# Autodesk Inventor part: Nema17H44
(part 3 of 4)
sketch "Эскиз112" dims "d52" = 8, "d53" = 4, "d55" = 5, "d56" = 11, "d57" = 12.2, "d58" = 6.1, "d60" = 36, "d61" = 45, "d62" = 50 (= 0.5 x h1), "d63" = 8.1, "d64" = 5, "d65" = 3, "d66" = 5.7
  geometry: L1 (-16.714, 19.577)-(-16.716, 18.63) reference; L2 (-16.08, 18.353)-(-16.08, 17.853) reference; L3 (-16.718, 17.574)-(-16.72, 16.633) reference; L4 (-16.08, 16.353)-(-16.08, 15.853) reference; L5 (-16.723, 15.571)-(-16.725, 14.636) reference; L6 (-16.08, 14.353)-(-16.08, 13.853) reference; L7 (-16.727, 13.569)-(-16.729, 12.639) reference; L8 (-16.08, 12.353)-(-16.08, 11.853) reference; L9 (-16.732, 11.566)-(-16.734, 10.642) reference; L10 (-16.08, 10.353)-(-16.08, 9.853) reference; L11 (-16.736, 9.563)-(-16.738, 8.645) reference; L12 (-16.08, 8.353)-(-16.08, 7.853) reference; L13 (-16.741, 7.56)-(-16.743, 6.648) reference; L14 (-16.08, 6.353)-(-16.08, 5.853) reference; L15 (-16.745, 5.556)-(-16.747, 4.651) reference; L16 (-16.08, 4.353)-(-16.08, 3.853) reference; L17 (-16.749, 3.553)-(-16.751, 2.654) reference; L18 (-16.08, 2.353)-(-16.08, 1.853) reference; L19 (-16.754, 1.55)-(-16.756, 0.657) reference; L20 (-16.08, 0.353)-(-16.08, -0.147) reference; L21 (-16.758, -0.453)-(-16.76, -1.339) reference; L22 (-16.08, -1.647)-(-16.08, -2.147) reference; L23 (-16.763, -2.457)-(-17, -108.975) reference; L24 (-29, -108.975)-(-29.55, 138.024) reference; L25 (-16.45, 138.024)-(-16.703, 24.622) reference; L26 (-16.08, 24.353)-(-16.08, 23.853) reference; L27 (-16.705, 23.582)-(-16.707, 22.625) reference; L28 (-16.08, 22.353)-(-16.08, 21.853) reference; L29 (-16.709, 21.58)-(-16.711, 20.628) reference; L30 (-16.08, 20.353)-(-16.08, 19.853) reference; L31 (-15.6, -108.962)-(-15.6, 138.038) reference; L32 (-30.4, 138.038)-(-30.4, -108.962) reference; L33 (-16.18, 1.853)-(-16.18, 2.353); L34 (-16.852, 2.606)-(-16.849, 3.602); L35 (-16.18, 3.853)-(-16.18, 4.353); L36 (-16.847, 4.602)-(-16.845, 5.606); L37 (-16.18, 5.853)-(-16.18, 6.353); L38 (-16.843, 6.598)-(-16.84, 7.609); L39 (-16.18, 7.853)-(-16.18, 8.353); L40 (-16.838, 8.595)-(-16.836, 9.613); L41 (-16.18, 9.853)-(-16.18, 10.353); L42 (-16.834, 10.591)-(-16.831, 11.617); L43 (-16.18, 11.853)-(-16.18, 12.353); L44 (-16.829, 12.588)-(-16.827, 13.62); L45 (-16.18, 13.853)-(-16.18, 14.353); L46 (-16.825, 14.584)-(-16.823, 15.624); L47 (-16.18, 15.853)-(-16.18, 16.353); L48 (-16.82, 16.581)-(-16.818, 17.627); L49 (-16.18, 17.853)-(-16.18, 18.353); L50 (-16.816, 18.577)-(-16.814, 19.63); L51 (-16.18, 19.853)-(-16.18, 20.353); L52 (-16.812, 20.574)-(-16.809, 21.633); L53 (-16.18, 21.853)-(-16.18, 22.353); L54 (-16.807, 22.571)-(-16.805, 23.637); L55 (-16.18, 23.853)-(-16.18, 24.353); L56 (-16.803, 24.568)-(-16.55, 138.024); L57 (-29.45, 138.024)-(-28.9, -108.975); L58 (-17.1, -108.975)-(-16.863, -2.41); L59 (-16.18, -2.147)-(-16.18, -1.647); L60 (-16.86, -1.386)-(-16.858, -0.406); L61 (-16.18, -0.147)-(-16.18, 0.353); L62 (-16.856, 0.61)-(-16.854, 1.598); L63 (-17, 22.5)-(0, 22.5) reference; L64 (-15.5, 22.5)-(-15.5, -0.147)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; C1 r 1 at (-14.5, 15.25) reference; C2 r 1 at (-14.5, 7.25) reference; A1 r 0.555 centre (-16.425, 19.103) between (-16.668, 19.602) and (-16.714, 19.577) reference; A2 r 0.555 centre (-16.425, 19.103) between (-16.716, 18.63) and (-16.668, 18.604) reference; A3 r 1 centre (-16.23, 19.503) between (-16.668, 18.604) and (-16.23, 18.503) reference; A4 r 0.15 centre (-16.23, 18.353) between (-16.08, 18.353) and (-16.23, 18.503) reference; A5 r 0.15 centre (-16.23, 17.853) between (-16.23, 17.703) and (-16.08, 17.853) reference; A6 r 1 centre (-16.23, 16.703) between (-16.23, 17.703) and (-16.668, 17.602) reference; A7 r 0.555 centre (-16.425, 17.103) between (-16.668, 17.602) and (-16.718, 17.574) reference; A8 r 0.555 centre (-16.425, 17.103) between (-16.72, 16.633) and (-16.668, 16.604) reference; A9 r 1 centre (-16.23, 17.503) between (-16.668, 16.604) and (-16.23, 16.503) reference; A10 r 0.15 centre (-16.23, 16.353) between (-16.08, 16.353) and (-16.23, 16.503) reference; A11 r 0.15 centre (-16.23, 15.853) between (-16.23, 15.703) and (-16.08, 15.853) reference; A12 r 1 centre (-16.23, 14.703) between (-16.23, 15.703) and (-16.668, 15.602) reference; A13 r 0.555 centre (-16.425, 15.103) between (-16.668, 15.602) and (-16.723, 15.571) reference; A14 r 0.555 centre (-16.425, 15.103) between (-16.725, 14.636) and (-16.668, 14.604) reference; A15 r 1 centre (-16.23, 15.503) between (-16.668, 14.604) and (-16.23, 14.503) reference; A16 r 0.15 centre (-16.23, 14.353) between (-16.08, 14.353) and (-16.23, 14.503) reference; A17 r 0.15 centre (-16.23, 13.853) between (-16.23, 13.703) and (-16.08, 13.853) reference; A18 r 1 centre (-16.23, 12.703) between (-16.23, 13.703) and (-16.668, 13.602) reference; A19 r 0.555 centre (-16.425, 13.103) between (-16.668, 13.602) and (-16.727, 13.569) reference; A20 r 0.555 centre (-16.425, 13.103) between (-16.729, 12.639) and (-16.668, 12.604) reference; A21 r 1 centre (-16.23, 13.503) between (-16.668, 12.604) and (-16.23, 12.503) reference; A22 r 0.15 centre (-16.23, 12.353) between (-16.08, 12.353) and (-16.23, 12.503) reference; A23 r 0.15 centre (-16.23, 11.853) between (-16.23, 11.703) and (-16.08, 11.853) reference; A24 r 1 centre (-16.23, 10.703) between (-16.23, 11.703) and (-16.668, 11.602) reference; A25 r 0.555 centre (-16.425, 11.103) between (-16.668, 11.602) and (-16.732, 11.566) reference; A26 r 0.555 centre (-16.425, 11.103) between (-16.734, 10.642) and (-16.668, 10.604) reference; A27 r 1 centre (-16.23, 11.503) between (-16.668, 10.604) and (-16.23, 10.503) reference; A28 r 0.15 centre (-16.23, 10.353) between (-16.08, 10.353) and (-16.23, 10.503) reference; A29 r 0.15 centre (-16.23, 9.853) between (-16.23, 9.703) and (-16.08, 9.853) reference; A30 r 1 centre (-16.23, 8.703) between (-16.23, 9.703) and (-16.668, 9.602) reference; A31 r 0.555 centre (-16.425, 9.103) between (-16.668, 9.602) and (-16.736, 9.563) reference; A32 r 0.555 centre (-16.425, 9.103) between (-16.738, 8.645) and (-16.668, 8.604) reference; A33 r 1 centre (-16.23, 9.503) between (-16.668, 8.604) and (-16.23, 8.503) reference; A34 r 0.15 centre (-16.23, 8.353) between (-16.08, 8.353) and (-16.23, 8.503) reference; A35 r 0.15 centre (-16.23, 7.853) between (-16.23, 7.703) and (-16.08, 7.853) reference; A36 r 1 centre (-16.23, 6.703) between (-16.23, 7.703) and (-16.668, 7.602) reference; A37 r 0.555 centre (-16.425, 7.103) between (-16.668, 7.602) and (-16.741, 7.56) reference; A38 r 0.555 centre (-16.425, 7.103) between (-16.743, 6.648) and (-16.668, 6.604) reference; A39 r 1 centre (-16.23, 7.503) between (-16.668, 6.604) and (-16.23, 6.503) reference; A40 r 0.15 centre (-16.23, 6.353) between (-16.08, 6.353) and (-16.23, 6.503) reference; A41 r 0.15 centre (-16.23, 5.853) between (-16.23, 5.703) and (-16.08, 5.853) reference; A42 r 1 centre (-16.23, 4.703) between (-16.23, 5.703) and (-16.668, 5.602) reference; A43 r 0.555 centre (-16.425, 5.103) between (-16.668, 5.602) and (-16.745, 5.556) reference; A44 r 0.555 centre (-16.425, 5.103) between (-16.747, 4.651) and (-16.668, 4.604) reference; A45 r 1 centre (-16.23, 5.503) between (-16.668, 4.604) and (-16.23, 4.503) reference; A46 r 0.15 centre (-16.23, 4.353) between (-16.08, 4.353) and (-16.23, 4.503) reference; A47 r 0.15 centre (-16.23, 3.853) between (-16.23, 3.703) and (-16.08, 3.853) reference; A48 r 1 centre (-16.23, 2.703) between (-16.23, 3.703) and (-16.668, 3.602) reference; A49 r 0.555 centre (-16.425, 3.103) between (-16.668, 3.602) and (-16.749, 3.553) reference; A50 r 0.555 centre (-16.425, 3.103) between (-16.751, 2.654) and (-16.668, 2.604) reference; A51 r 1 centre (-16.23, 3.503) between (-16.668, 2.604) and (-16.23, 2.503) reference; A52 r 0.15 centre (-16.23, 2.353) between (-16.08, 2.353) and (-16.23, 2.503) reference; A53 r 0.15 centre (-16.23, 1.853) between (-16.23, 1.703) and (-16.08, 1.853) reference; A54 r 1 centre (-16.23, 0.703) between (-16.23, 1.703) and (-16.668, 1.602) reference; A55 r 0.555 centre (-16.425, 1.103) between (-16.668, 1.602) and (-16.754, 1.55) reference; A56 r 0.555 centre (-16.425, 1.103) between (-16.756, 0.657) and (-16.668, 0.604) reference; A57 r 1 centre (-16.23, 1.503) between (-16.668, 0.604) and (-16.23, 0.503) reference; A58 r 0.15 centre (-16.23, 0.353) between (-16.08, 0.353) and (-16.23, 0.503) reference; A59 r 0.15 centre (-16.23, -0.147) between (-16.23, -0.297) and (-16.08, -0.147) reference; A60 r 1 centre (-16.23, -1.297) between (-16.23, -0.297) and (-16.668, -0.398) reference; A61 r 0.555 centre (-16.425, -0.897) between (-16.668, -0.398) and (-16.758, -0.453) reference; A62 r 0.555 centre (-16.425, -0.897) between (-16.76, -1.339) and (-16.668, -1.396) reference; A63 r 1 centre (-16.23, -0.497) between (-16.668, -1.396) and (-16.23, -1.497) reference; A64 r 0.15 centre (-16.23, -1.647) between (-16.08, -1.647) and (-16.23, -1.497) reference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; 32 further points; 1 other entity
  constraints: 192 point on circle, 94 centre point, 70 end point, 13 point on line, 8 tangent, 4 equal radius, 3 coincident, 3 vertical, 2 collinear, 2 perpendicular, 116 other
  dimensions: "d773" = 0.1 radial gap between concentric circles of A55 A89; "d774" = 0.1 distance between parallel lines of L31 L64; "d775" = 4 diameter of A175; "d776" = 4 diameter of A176 (derived); "d777" = 3 distance between parallel lines of L64 L65; "d778" = 3.5 distance between parallel lines of L53 L67; "d786" = 3.2 radius of A177; "d787" = 2 radius of A179 (derived)
extrude "Выдавливание87" join sketch "Эскиз112" distance "d779" = 6; taper "d780" = 0 deg
chamfer "Фаска34" distance "d782" = 1; stored, may be unused: second distance "d783" = 2, angle "d784" = 45 deg
fillet "Сопряжение34" dims "d788" = 3.2
fillet "Сопряжение35" dims "d789" = 5
fillet "Сопряжение36" dims "d790" = 1
chamfer "Фаска35" distance "d792" = 1; stored, may be unused: second distance "d793" = 2, angle "d794" = 45 deg
sketch "Эскиз113"
  geometry: L1 (9, 17.98)-(7.86, 16.84); L2 (7.86, 16.84)-(9, 15.7); L3 (9, 16.5)-(9, 13.5) reference; L4 (3, 16.5)-(9, 16.5) reference; L5 (9, 17.18)-(9, 17.23) reference; L6 (9, 17.18)-(9, 16.5); L7 (9, 17.98)-(9, 15.7); 7 further points
  constraints: 8 end point, 3 point on line, 2 perpendicular, 1 collinear, 1 horizontal alignment, 1 midpoint, 1 vertical alignment
  dimensions: "d795" = 0.8 distance from line of point (8.2, 16.5) L3
extrude "Выдавливание88" cut sketch "Эскиз113" stored distance "d796" = 6; taper "d797" = 0 deg
fillet "Сопряжение38" dims "d798" = 1
fillet "Сопряжение39" dims "d799" = 0.4
chamfer "Фаска36" distance "d800" = 1; stored, may be unused: second distance "d801" = 2, angle "d802" = 45 deg
sketch "Эскиз114"
  geometry: L1 (22, 22.5)-(22, 0) reference; L2 (-1, 22.5)-(22, 22.5) reference; L3 (-3, 2)-(-3, 20.5) reference; L4 (22, 0)-(-1, 0) reference; C1 r 1 at (14.5, 7.25) reference; C2 r 1 at (14.5, 15.25) reference; C3 r 1 at (2.5, 15.25) reference; C4 r 1 at (2.5, 7.25) reference; C5 r 2 at (14.5, 7.25); C6 r 2 at (14.5, 15.25); C7 r 2 at (2.5, 7.25); C8 r 2 at (2.5, 15.25); A1 r 2 centre (-1, 20.5) between (-1, 22.5) and (-3, 20.5) reference; A2 r 2 centre (-1, 2) between (-3, 2) and (-1, 0) reference; 1 further point
  constraints: 4 centre point
  dimensions: "d803" = 1 radial gap between concentric circles of C1 C5; "d804" = 1 radial gap between concentric circles of C2 C6; "d805" = 1 radial gap between concentric circles of C4 C7; "d806" = 1 radial gap between concentric circles of C3 C8
extrude "Выдавливание89" cut sketch "Эскиз114" distance "d807" = 1.5; taper "d808" = 0 deg
chamfer "Фаска37" distance "d809" = 0.5; stored, may be unused: second distance "d810" = 2, angle "d811" = 45 deg
sketch "Эскиз115"
  geometry: L1 (22, 22.5)-(22, 0) reference; L2 (-1, 22.5)-(22, 22.5) reference; L3 (-3, 2)-(-3, 20.5) reference; L4 (22, 0)-(-1, 0) reference; C1 r 2.5 at (2.5, 7.25) reference; C2 r 2.5 at (14.5, 7.25) reference; C3 r 2.5 at (14.5, 15.25) reference; C4 r 2.5 at (2.5, 15.25) reference; C5 r 2.5 at (14.5, 15.25) reference; C6 r 2 at (14.5, 15.25) reference; C7 r 2 at (14.5, 7.25) reference; C8 r 2 at (2.5, 7.25) reference; C9 r 2 at (2.5, 15.25) reference; C10 r 1 at (2.5, 15.25) reference; C11 r 1 at (14.5, 15.25) reference; C12 r 1 at (14.5, 7.25) reference; C13 r 1 at (2.5, 7.25) reference; C14 r 1.85 at (2.5, 7.25); C15 r 1.85 at (2.5, 15.25); C16 r 1.85 at (14.5, 15.25); C17 r 1.85 at (14.5, 7.25); A1 r 2 centre (-1, 20.5) between (-1, 22.5) and (-3, 20.5) reference; A2 r 2 centre (-1, 2) between (-3, 2) and (-1, 0) reference; 1 further point
  constraints: 4 centre point
  dimensions: "d817" = 0.15 radial gap between concentric circles of C8 C14; "d818" = 0.15 radial gap between concentric circles of C9 C15 (derived); "d819" = 0.15 radial gap between concentric circles of C6 C16 (derived); "d820" = 0.15 radial gap between concentric circles of C7 C17 (derived)
extrude "Выдавливание90" join sketch "Эскиз115" distance "d812" = 1.3; taper "d813" = 0 deg
chamfer "Фаска38" distance "d814" = 0.5; stored, may be unused: second distance "d815" = 2, angle "d816" = 45 deg
fillet "Сопряжение40" dims "d821" = 1
sketch "Эскиз116"
  geometry: C1 r 1.5 at (-5.5, 5.05) reference; C2 r 1.5 at (-29.5, 5.05) reference; C3 r 1.5 at (-29.5, 17.05) reference; C4 r 1.5 at (-5.5, 17.05) reference; C5 r 3.5 at (-5.5, 5.05); C6 r 3.5 at (-5.5, 5.05) reference; C7 r 3.5 at (-29.5, 5.05); C8 r 3.5 at (-29.5, 17.05); C9 r 3.5 at (-5.5, 17.05); 1 further point
  constraints: 4 centre point
  dimensions: "d822" = 2 radial gap between concentric circles of C1 C5; "d823" = 2 radial gap between concentric circles of C2 C7; "d824" = 2 radial gap between concentric circles of C3 C8; "d825" = 2 radial gap between concentric circles of C4 C9
extrude "Выдавливание91" join sketch "Эскиз116" distance "d826" = 0.7; taper "d827" = 0 deg
sketch "Эскиз117"
  geometry: L1 (1.5, -1.4)-(-35, -1.4); L2 (-35, -1.4)-(-35, 23.5); L3 (-35, 23.5)-(1.5, 23.5); L4 (1.5, 23.5)-(1.5, -1.4); L5 (-35, -1.4)-(0, -1.4) reference; L6 (0, 23.5)-(-35, 23.5) reference; L7 (1.5, 0)-(1.5, 22.1) reference; L8 (-35, 0)-(-35, 22.1) reference; C1 r 3.5 at (-5.5, 5.05) reference; C2 r 3.5 at (-5.5, 17.05) reference; C3 r 3.5 at (-29.5, 5.05) reference; C4 r 3.5 at (-29.5, 17.05) reference; C5 r 3.65 at (-5.5, 5.05); C6 r 3.65 at (-29.5, 5.05); C7 r 3.65 at (-29.5, 17.05); C8 r 3.65 at (-5.5, 17.05); 1 further point
  constraints: 8 end point, 4 centre point, 4 collinear, 3 equal radius, 2 parallel, 1 horizontal, 1 perpendicular
  dimensions: "d828" = 0.15 radial gap between concentric circles of C1 C5
extrude "Выдавливание92" new body sketch "Эскиз117" distance "d829" = 1; taper "d830" = 0 deg
sketch "Эскиз118"
  geometry: L1 (-35, -1.4)-(1.5, -1.4) reference; L2 (1.5, -1.4)-(1.5, 23.5) reference; L3 (1.5, 23.5)-(-35, 23.5) reference; L4 (-35, 23.5)-(-35, -1.4) reference; C1 r 1.5 at (-5.5, 5.05) reference; C2 r 1.5 at (-5.5, 17.05) reference; C3 r 1.5 at (-29.5, 17.05) reference; C4 r 1.5 at (-29.5, 5.05) reference; 1 further point
extrude "Выдавливание93" join sketch "Эскиз118" distance "d831" = 1; taper "d832" = 0 deg
chamfer "Фаска39" distance "d833" = 0.5; stored, may be unused: second distance "d834" = 2, angle "d835" = 45 deg
fillet "Сопряжение41" dims "d836" = 1
fillet "Сопряжение42" dims "d837" = 4
fillet "Сопряжение43" dims "d838" = 1
sketch "Эскиз119"
  geometry: L1 (-10, 3.45)-(-2, 11.45); L2 (-2, 0)-(-2, 22.9) reference; L3 (-10, 19.45)-(-2, 11.45); L4 (-10, 3.45)-(-10, 2.364); L5 (-10, 2.364)-(-2, 2.003); L6 (-10, 19.45)-(-10, 20.536); L7 (-10, 20.536)-(-2, 20.897); L8 (-2, -1)-(-17.928, -0.281); L9 (-29.142, 11.45)-(-29.142, 11.45); L10 (-29.142, 11.45)-(-2, 11.45); L11 (-29.142, 11.45)-(-29.142, 11.45); L12 (-2, 23.9)-(-17.928, 23.181); L13 (-2, -1)-(-2, 23.9); A1 r 11.743 centre (-17.399, 11.45) between (-29.142, 11.45) and (-17.928, -0.281); A2 r 11.743 centre (-17.399, 11.45) between (-17.928, 23.181) and (-29.142, 11.45); A3 r 10 centre (-16.142, 11.45) between (-9.071, 18.521) and (-9.071, 4.379); 4 further points
  constraints: 24 end point, 6 point on circle, 6 point on line, 4 symmetric about line, 3 centre point, 3 equal length, 3 tangent, 3 vertical, 2 midpoint, 2 perpendicular, 1 parallel, 1 vertical alignment, 1 other
  dimensions: "d839" = 8 horizontal distance of L1.start L1.end; "d840" = 20 diameter of A3; "d841" = 3 distance between parallel lines of L12 L7; "d842" = 3 distance edge to line of A3 L9; "d843" = 1.8 distance edge to line of A3 L8; "d844" = 3 dimension on A3 A1
extrude "Выдавливание94" join sketch "Эскиз119" stored distance "d845" = 1; taper "d846" = 0 deg
sketch "Эскиз120"
  geometry: L1 (-0.5, 23.5)-(34, 23.5) reference; L2 (-1.5, -0.4)-(-1.5, 22.5) reference; L3 (34, -1.4)-(-0.5, -1.4) reference; L4 (35, 22.5)-(35, -0.4) reference; L5 (-5.539, -12.282)-(42.535, -12.282); L6 (42.535, -12.282)-(42.535, 30.617); L7 (42.535, 30.617)-(-5.539, 30.617); L8 (-5.539, 30.617)-(-5.539, -12.282); C1 r 3.65 at (5.5, 17.05) reference; C2 r 3.65 at (29.5, 17.05) reference; C3 r 3.65 at (29.5, 5.05) reference; C4 r 3.65 at (5.5, 5.05) reference; C5 r 3.25 at (29.5, 5.05); C6 r 3.25 at (29.5, 17.05); C7 r 3.25 at (5.5, 5.05); C8 r 3.25 at (5.5, 17.05); A1 r 1 centre (34, 22.5) between (35, 22.5) and (34, 23.5) reference; A2 r 1 centre (-0.5, 22.5) between (-0.5, 23.5) and (-1.5, 22.5) reference; A3 r 1 centre (-0.5, -0.4) between (-1.5, -0.4) and (-0.5, -1.4) reference; A4 r 1 centre (34, -0.4) between (34, -1.4) and (35, -0.4) reference; 1 further point
  constraints: 8 end point, 4 centre point, 4 coincident, 3 equal radius, 2 parallel, 1 horizontal, 1 perpendicular
  dimensions: "d847" = 6.5 diameter of C5
extrude "Выдавливание95" cut sketch "Эскиз120" distance "d848" = 40; taper "d849" = 0 deg
fillet "Сопряжение44" dims "d850" = 1
sketch "Эскиз121"
  geometry: C1 r 3.25 at (0, 0) reference; C2 r 3.25 at (-24, 0) reference; C3 r 3.25 at (-24, 12) reference; C4 r 3.25 at (0, 12) reference; C5 r 1.5 at (0, 0); C6 r 1.5 at (-24, 0); C7 r 1.5 at (-24, 12); C8 r 1.5 at (0, 12); 1 further point
  constraints: 4 centre point, 3 equal radius, 2 coincident, 2 concentric
  dimensions: "d851" = 3 diameter of C5
extrude "Выдавливание96" join sketch "Эскиз121" distance "d852" = 2; taper "d853" = 0 deg
sketch "Эскиз122"
  geometry: L1 (-26.142, -9.784)-(-26.142, 34.23); A1 r 11.743 centre (-17.399, 11.45) between (-20.007, 22.9) and (-20.007, 0) reference; A2 r 10 centre (-16.142, 11.45) between (-9.071, 18.521) and (-9.071, 4.379) reference; 1 further point
  constraints: 2 end point, 1 tangent, 1 vertical
feature "ВыдавПврх1" sketch "Эскиз122" dims "d854" = 10, "d855" = 0
sketch "Эскиз123"
  geometry: L1 (0, 0)-(0, 44.015) reference; L2 (-1, 33.684)-(-35.5, 33.684) reference; C1 r 2 at (-18.25, 21.234); 3 further points
  constraints: 1 centre point, 1 horizontal alignment, 1 midpoint, 1 vertical alignment
  dimensions: "d859" = 4 diameter of C1
extrude "Выдавливание97" cut sketch "Эскиз123" stored distance "d857" = 10; taper "d858" = 0 deg
sketch "Эскиз124"
  geometry: L1 (-0.04, 32.966)-(-36.46, 32.966) reference; L2 (-36.5, 9.784)-(-36.5, 32.684) reference; C1 r 3.722 at (-18.25, 21.234); 5 further points
  constraints: 2 midpoint, 1 centre point, 1 horizontal alignment, 1 vertical alignment, 1 other
extrude "Выдавливание98" join sketch "Эскиз124" distance "d860" = 5.5; taper "d861" = 0 deg
fillet "Сопряжение45" dims "d862" = 1
chamfer "Фаска40" distance "d863" = 0.5; stored, may be unused: second distance "d864" = 2, angle "d865" = 45 deg
chamfer "Фаска41" distance "d866" = 0.5; stored, may be unused: second distance "d867" = 2, angle "d868" = 45 deg
sketch "Эскиз125"
  geometry: L1 (-26.835, 267.57)-(39.543, 267.57); L2 (39.543, 267.57)-(39.543, 218.972); L3 (39.543, 218.972)-(-26.835, 218.972); L4 (-26.835, 218.972)-(-26.835, 267.57); 2 further points
  constraints: 8 end point, 2 parallel, 1 horizontal, 1 perpendicular, 1 other
extrude "Выдавливание99" cut sketch "Эскиз125" stored distance "d869" = 10; taper "d870" = 0 deg
node "РабПлоскость13"
sketch "Эскиз128"
  geometry: 1 further point
sketch "Эскиз130"
  geometry: L1 (26, 235.212)-(-0.106, 235.45) reference; L2 (26, 258.788)-(26, 235.212) reference; L3 (-0.106, 258.55)-(26, 258.788) reference; L4 (-11.55, 247)-(-11.55, 223.788); L5 (-11.55, 223.788)-(26, 223.788); L6 (30, 258.788)-(26, 258.788) reference; L7 (26, 223.788)-(26, 258.788); C1 r 2 at (16, 247) reference; C2 r 8.581 at (0, 247) reference; A1 r 11.55 centre (0, 247) between (-0.106, 258.55) and (-0.106, 235.45) reference; 2 further points
  constraints: 6 end point, 2 vertical, 1 perpendicular, 1 point on circle
  dimensions: "d882" = 35 distance between parallel lines of L6 L5
extrude "Выдавливание103" join sketch "Эскиз130" distance "d883" = 13; taper "d884" = 0 deg
fillet "Сопряжение46" dims "d885" = 8
sketch "Эскиз131"
  geometry: C1 r 3 at (0, 247) reference; C2 r 6.55 at (0, 247); 1 further point
  constraints: 1 centre point, 1 coincident
  dimensions: "d886" = 13.1 diameter of C2
extrude "Выдавливание104" cut sketch "Эскиз131" distance "d887" = 4.2; taper "d888" = 0 deg
sketch "Эскиз132"
  geometry: C1 r 6.55 at (0, 247) reference; C2 r 6.55 at (0, 247); 1 further point
  constraints: 1 centre point, 1 coincident
  dimensions: "d889" = 13.1 diameter of C2
extrude "Выдавливание105" cut sketch "Эскиз132" distance "d890" = 4.2; taper "d891" = 0 deg
sketch "Эскиз133"
  geometry: C1 r 6.55 at (0, 0) reference; C2 r 3.5 at (0, 0); 1 further point
  constraints: 1 centre point, 1 coincident
  dimensions: "d892" = 7 diameter of C2
extrude "Выдавливание106" cut sketch "Эскиз133" distance "d893" = 5; taper "d894" = 0 deg
chamfer "Фаска42" distance "d895" = 0.8; stored, may be unused: second distance "d896" = 2, angle "d897" = 45 deg
sketch "Эскиз134"
  geometry: L1 (-3.55, 223.788)-(26, 223.788) reference; L2 (26, 223.788)-(26, 258.788) reference; L3 (26, 258.788)-(-0.106, 258.55) reference; L4 (-11.55, 247)-(-11.55, 231.788) reference; L5 (-0.106, 235.45)-(26, 235.212); L6 (-0.106, 235.45)-(-1262.04, 247); L7 (26, 258.788)-(-0.106, 258.55) reference; L8 (0, 247)-(-1262.04, 247); C1 r 7.35 at (0, 247) reference; A1 r 8 centre (-3.55, 231.788) between (-11.55, 231.788) and (-3.55, 223.788) reference; A2 r 11.55 centre (0, 247) between (-0.106, 258.55) and (-11.55, 247) reference; A3 r 11.55 centre (0, 247) between (-11.55, 247) and (-0.106, 235.45); 1 further point
  constraints: 6 end point, 2 point on circle, 2 point on line, 1 centre point, 1 coincident, 1 collinear, 1 equal length, 1 line through centre, 1 tangent
extrude "Выдавливание107" cut sketch "Эскиз134" distance "d898" = 8; taper "d899" = 0 deg
fillet "Сопряжение47" dims "d900" = 8
sketch "Эскиз135"
  geometry: L1 (2.945, 229.788)-(-20, 229.788); L2 (-20, 229.788)-(-20, 252.733); L3 (3.55, 223.788)-(-26, 223.788) reference; L4 (-26, 233.888)-(-26, 203.688) reference; L5 (-26, 258.788)-(0.106, 258.55) reference; L6 (-26, 258.788)-(-26, 233.888) reference; C1 r 2 at (-20, 229.788); C2 r 2 at (-20, 252.733); C3 r 2 at (2.945, 229.788); C4 r 6 at (-20, 229.788); C5 r 5.91 at (2.945, 229.788); C6 r 6 at (-20, 252.733); A1 r 8 centre (3.55, 231.788) between (3.55, 223.788) and (11.55, 231.788) reference; 1 further point
  constraints: 6 centre point, 5 tangent, 4 end point, 3 coincident, 2 equal radius, 2 perpendicular, 1 horizontal, 1 horizontal alignment, 1 vertical alignment
  dimensions: "d901" = 4 diameter of C2; "d902" = 6 distance from line of L3 L1.end
extrude "Выдавливание108" cut sketch "Эскиз135" distance "d903" = 9; taper "d904" = 0 deg
chamfer "Фаска43" distance "d905" = 0.8; stored, may be unused: second distance "d906" = 2, angle "d907" = 45 deg
sketch "Эскиз136"
  geometry: L1 (-5.94, 252.94)-(5.94, 241.06); L2 (0, 247)-(-9.427, 237.573); L3 (-11.55, 247)-(-11.55, 231.788) reference; C1 r 1.25 at (-5.94, 252.94); C2 r 2.975 at (-5.94, 252.94); C3 r 6.55 at (0, 247) reference; C4 r 2.975 at (5.94, 241.06); C5 r 1.25 at (5.94, 241.06); 1 further point
  constraints: 4 centre point, 4 end point, 3 coincident, 2 symmetric about line, 1 midpoint, 1 perpendicular, 2 other
  dimensions: "d908" = 2.5 diameter of C1; "d909" = 5.95 diameter of C2; "d910" = 0.6 dimension on C1 C3; "d911" = 45 deg angle of L3 L1
extrude "Выдавливание109" cut sketch "Эскиз136" distance "d912" = 37; taper "d913" = 0 deg
chamfer "Фаска44" distance "d914" = 0.8; stored, may be unused: second distance "d915" = 2, angle "d916" = 45 deg
sketch "Эскиз137"
  geometry: L1 (11.9, 224.059)-(11.9, 220.636) reference; L2 (16.9, 220.636)-(11.9, 220.636) reference; L3 (16.9, 220.636)-(16.9, 255.636) reference; L4 (16.9, 255.636)-(3.9, 255.636) reference; L5 (3.9, 232.06)-(3.9, 255.636) reference; L6 (16.1, 251.581)-(16.1, 247.581) reference; L7 (16.1, 228.636)-(16.1, 224.636) reference; L8 (16.1, 251.581)-(7.9, 251.581) reference; L9 (16.1, 247.581)-(7.9, 247.581) reference; L10 (16.1, 228.636)-(10.499, 228.636) reference; L11 (16.1, 224.636)-(11.883, 224.636) reference; C1 r 2 at (10.4, 238.136); 4 further points; 1 other entity
  constraints: 2 midpoint, 1 centre point, 1 horizontal alignment, 1 vertical alignment, 1 other
  dimensions: "d917" = 4 diameter of C1
extrude "Выдавливание110" cut sketch "Эскиз137" distance "d918" = 17; taper "d919" = 0 deg
chamfer "Фаска45" distance "d920" = 0.8; stored, may be unused: second distance "d921" = 2, angle "d922" = 45 deg
sketch "Эскиз138"
  geometry: L1 (12.2, 32.657)-(12.2, 19.557) reference; L2 (12.2, 8.055)-(12.2, 4.055) reference; L3 (13, 0)-(0, 0) reference; L4 (12.2, 19.557)-(6.5, 13.806); L5 (6.5, 13.806)-(12.2, 8.055); C1 r 2 at (6.5, 13.806); 3 further points
  constraints: 4 end point, 1 centre point, 1 equal length, 1 midpoint, 1 vertical alignment, 1 other
  dimensions: "d923" = 4 diameter of C1
extrude "Выдавливание111" cut sketch "Эскиз138" distance "d924" = 25; taper "d925" = 0 deg
chamfer "Фаска46" distance "d926" = 0.8; stored, may be unused: second distance "d927" = 2, angle "d928" = 45 deg
fillet "Сопряжение48" dims "d929" = 1
sketch "Эскиз139"
  geometry: L1 (10.4, 242.136)-(10.4, 234.136); L2 (8.75, 242.136)-(8.75, 234.136); L3 (12.05, 234.136)-(12.05, 242.136); C1 r 2 at (10.4, 238.136) reference; A1 r 1.65 centre (10.4, 242.136) between (12.05, 242.136) and (8.75, 242.136); A2 r 1.65 centre (10.4, 234.136) between (8.75, 234.136) and (12.05, 234.136); 2 further points
  constraints: 8 end point, 4 point on circle, 4 tangent, 2 centre point, 1 coincident, 1 midpoint, 1 parallel, 1 vertical
  dimensions: "d930" = 1.65 radius of A2; "d931" = 8 distance of L1.start L1.end
extrude "Выдавливание112" cut sketch "Эскиз139" distance "d932" = 25; taper "d933" = 0 deg
chamfer "Фаска47" distance "d934" = 2.4; stored, may be unused: second distance "d935" = 2, angle "d936" = 45 deg
sketch "Эскиз141"
  geometry: L1 (-136.99, 238.639)-(-111.01, 238.639); L2 (-111.01, 238.639)-(-136.99, 238.639); L3 (-124, 261.139)-(-136.99, 238.639); C1 r 3 at (-124, 246.139) reference; C2 r 1.4 at (-124, 261.139) reference; C3 r 1.4 at (-111.01, 238.639) reference; C4 r 2 at (-136.99, 238.639); A1 r 15 centre (-124, 246.139) between (-124, 261.139) and (-136.99, 238.639); 1 further point
  constraints: 6 end point, 2 centre point, 2 point on circle, 1 coincident, 1 collinear, 1 equal length
  dimensions: "d937" = 4 diameter of C4
extrude "Выдавливание113" cut sketch "Эскиз141" distance "d938" = 10; taper "d939" = 0 deg
sketch "Эскиз142"
  geometry: L1 (16, -22)-(16, 0) reference; L2 (-13, -25)-(13, -25) reference; L3 (-16, 0)-(-16, -22) reference; L4 (-3.85, -13.848)-(3.85, -13.848) reference; L5 (3.85, -10.848)-(3.85, -13.848) reference; L6 (3.85, -10.848)-(-3.85, -10.848) reference; L7 (-3.85, -13.848)-(-3.85, -10.848) reference; L8 (-5.5, -17.924)-(-5.5, -22.924) reference; L9 (-5.5, -22.924)-(5.5, -22.924) reference; L10 (5.5, -22.924)-(5.5, -17.924) reference; L11 (5.5, -17.924)-(-5.5, -17.924) reference; L12 (18, 0)-(18, -22) reference; L13 (-18, -22)-(-18, 0) reference; L14 (13, -27)-(-13, -27) reference; L15 (-3.85, -13.848)-(3.85, -13.848) reference; L16 (-3.85, -10.848)-(-3.85, -13.848) reference; L17 (3.85, -10.848)-(-3.85, -10.848) reference; L18 (3.85, -13.848)-(3.85, -10.848) reference; L19 (-7.5, -22.924)-(7.5, -22.924) reference; L20 (-7.5, -17.924)-(-7.5, -22.924) reference; L21 (7.5, -17.924)-(-7.5, -17.924) reference; L22 (7.5, -22.924)-(7.5, -17.924) reference; L23 (-12.99, -10)-(-12.99, -5); L24 (-11.34, -10)-(-11.34, -5); L25 (-14.64, -5)-(-14.64, -10); L26 (12.99, -10)-(12.99, -5); L27 (14.64, -10)-(14.64, -5); L28 (11.34, -5)-(11.34, -10); L29 (0, 12.5)-(0, 17.5); L30 (1.65, 12.5)-(1.65, 17.5); L31 (-1.65, 17.5)-(-1.65, 12.5); C1 r 4.75 at (0, 0) reference; C2 r 2 at (-12.99, -7.5) reference; C3 r 2.7 at (0, 15) reference; C4 r 4.05 at (0, 0) reference; C5 r 2.7 at (12.99, -7.5) reference; A1 r 3 centre (13, -22) between (13, -25) and (16, -22) reference; A2 r 3 centre (-13, -22) between (-16, -22) and (-13, -25) reference; A3 r 16 centre (0, 0) between (16, 0) and (-16, 0) reference; A4 r 18 centre (0, 0) between (18, 0) and (-18, 0) reference; A5 r 5 centre (-13, -22) between (-18, -22) and (-13, -27) reference; A6 r 5 centre (13, -22) between (13, -27) and (18, -22) reference; A7 r 1.65 centre (-12.99, -10) between (-14.64, -10) and (-11.34, -10); A8 r 1.65 centre (-12.99, -5) between (-11.34, -5) and (-14.64, -5); A9 r 1.65 centre (12.99, -10) between (11.34, -10) and (14.64, -10); A10 r 1.65 centre (12.99, -5) between (14.64, -5) and (11.34, -5); A11 r 1.65 centre (0, 12.5) between (-1.65, 12.5) and (1.65, 12.5); A12 r 1.65 centre (0, 17.5) between (1.65, 17.5) and (-1.65, 17.5); 1 further point
  constraints: 24 end point, 12 point on circle, 12 tangent, 7 parallel, 6 centre point, 3 midpoint, 2 equal radius, 1 vertical
  dimensions: "d940" = 5 distance of L23.start L23.end; "d941" = 1.65 radius of A8
extrude "Выдавливание114" cut sketch "Эскиз142" distance "d942" = 10; taper "d943" = 0 deg
sketch "Эскиз144"
  geometry: L1 (-129.5, 221.115)-(-118.5, 221.115); L2 (-118.5, 221.115)-(-118.5, 230.315); L3 (-118.5, 230.315)-(-129.5, 230.315); L4 (-129.5, 230.315)-(-129.5, 221.115); L5 (-126.85, 230.315)-(-121.15, 230.315); L6 (-121.15, 230.315)-(-121.15, 237.391); L7 (-121.15, 237.391)-(-126.85, 237.391); L8 (-126.85, 237.391)-(-126.85, 230.315); L9 (-126.85, 232.291)-(-126.85, 235.291) reference; L10 (-121.15, 235.291)-(-121.15, 232.291) reference; L11 (-129.5, 228.215)-(-129.5, 223.215) reference; L12 (-118.5, 223.215)-(-118.5, 228.215) reference; L13 (-131.5, 228.215)-(-116.5, 228.215) reference; L14 (-116.5, 223.215)-(-131.5, 223.215) reference; L15 (-127.85, 235.291)-(-120.15, 235.291) reference; L16 (-124, 243.639)-(-124, 248.639); L17 (-119.95, 243.639)-(-119.95, 248.639); L18 (-128.05, 248.639)-(-128.05, 243.639); C1 r 3 at (-124, 246.139) reference; C2 r 4.05 at (-124, 246.139) reference; A1 r 4.05 centre (-124, 243.639) between (-128.05, 243.639) and (-119.95, 243.639); A2 r 4.05 centre (-124, 248.639) between (-119.95, 248.639) and (-128.05, 248.639); 2 further points
  constraints: 24 end point, 5 parallel, 5 tangent, 4 collinear, 4 point on circle, 2 centre point, 2 horizontal, 2 perpendicular, 1 midpoint, 1 point on line, 1 vertical
  dimensions: "d955" = 2.1 distance between parallel lines of L13 L3; "d956" = 2.1 distance between parallel lines of L14 L1; "d957" = 2.1 distance between parallel lines of L15 L7; "d958" = 2.5 distance of C1.centre L16.end
extrude "Выдавливание115" cut sketch "Эскиз144" distance "d953" = 4; taper "d954" = 0 deg
sketch "Эскиз145"
  geometry: L1 (-126.85, 29.291)-(-126.85, 32.291) reference; L2 (-121.15, 32.291)-(-121.15, 29.291) reference; L3 (-120.15, 32.291)-(-120.15, 29.291) reference; L4 (-120.15, 29.291)-(-127.85, 29.291) reference; L5 (-127.85, 32.291)-(-120.15, 32.291) reference; L6 (-127.85, 29.291)-(-127.85, 32.291) reference; L7 (-131.5, 36.367)-(-131.5, 41.367) reference; L8 (-129.5, 41.367)-(-129.5, 36.367) reference; L9 (-116.5, 36.367)-(-131.5, 36.367) reference; L10 (-131.5, 41.367)-(-116.5, 41.367) reference; L11 (-118.5, 36.367)-(-118.5, 41.367) reference; L12 (-116.5, 41.367)-(-116.5, 36.367) reference; L13 (-129.5, 228.215)-(-129.5, 223.215) reference; L14 (-129.5, 223.215)-(-131.5, 223.215) reference; L15 (-131.5, 223.215)-(-131.5, 228.215) reference; L16 (-131.5, 228.215)-(-129.5, 228.215) reference; L17 (-116.5, 223.215)-(-118.5, 223.215) reference; L18 (-118.5, 223.215)-(-118.5, 228.215) reference; L19 (-118.5, 228.215)-(-116.5, 228.215) reference; L20 (-116.5, 228.215)-(-116.5, 223.215) reference; L21 (-120.15, 235.291)-(-120.15, 232.291) reference; L22 (-120.15, 232.291)-(-121.15, 232.291) reference; L23 (-121.15, 235.291)-(-121.15, 232.291) reference; L24 (-121.15, 235.291)-(-120.15, 235.291) reference; L25 (-126.85, 232.291)-(-126.85, 235.291) reference; L26 (-126.85, 232.291)-(-127.85, 232.291) reference; L27 (-127.85, 232.291)-(-127.85, 235.291) reference; L28 (-127.85, 235.291)-(-126.85, 235.291) reference; 1 further point
extrude "Выдавливание116" join sketch "Эскиз145" distance "d959" = 4; taper "d960" = 0 deg
fillet "Сопряжение49" dims "d961" = 1
mirror "Зеркальное отражение10"
sketch "Эскиз146"
  geometry: L1 (0, 282.577)-(26.097, 282.338) reference; L2 (0, 249.577)-(0, 282.577) reference; L3 (29.55, 249.577)-(0, 249.577) reference; L4 (36.55, 271.788)-(36.55, 256.577) reference; L5 (6, 252.077)-(6, 257.077); L6 (7.65, 252.077)-(7.65, 257.077); L7 (4.35, 257.077)-(4.35, 252.077); L8 (6, 280.022)-(6, 275.022); L9 (7.65, 280.022)-(7.65, 275.022); L10 (4.35, 275.022)-(4.35, 280.022); L11 (28.945, 257.077)-(28.945, 252.077); L12 (30.595, 257.077)-(30.595, 252.077); L13 (27.295, 252.077)-(27.295, 257.077); L14 (20.042, 267.849)-(20.079, 263.849); L15 (26.106, 260.189)-(0, 259.95) reference; L16 (23.042, 267.876)-(23.078, 263.876); L17 (17.079, 263.821)-(17.042, 267.821); L18 (31.94, 275.728)-(31.94, 279.728); L19 (34.94, 275.728)-(34.94, 279.728); L20 (28.94, 279.728)-(28.94, 275.728); L21 (26, 274.288)-(26, 269.288); L22 (29.5, 274.288)-(29.5, 269.288); L23 (22.5, 269.288)-(22.5, 274.288); C1 r 2.8 at (28.945, 254.577) reference; C2 r 2.8 at (6, 254.577) reference; C3 r 2.8 at (6, 277.522) reference; C4 r 3 at (20.06, 265.849); C5 r 1.25 at (31.94, 277.728) reference; C6 r 3.5 at (26, 271.788) reference; A1 r 7 centre (29.55, 256.577) between (29.55, 249.577) and (36.55, 256.577) reference; A2 r 10.55 centre (26, 271.788) between (36.55, 271.788) and (26.097, 282.338) reference; A3 r 2.05 centre (20.06, 265.849) between (19.776, 267.879) and (22.09, 265.564) reference; A4 r 7.35 centre (26, 271.788) between (29.91, 278.012) and (19.776, 267.879) reference; A5 r 2.05 centre (31.94, 277.728) between (32.224, 275.698) and (29.91, 278.012) reference; A6 r 7.35 centre (26, 271.788) between (22.09, 265.564) and (32.224, 275.698) reference; A7 r 1.65 centre (6, 252.077) between (4.35, 252.077) and (7.65, 252.077); A8 r 1.65 centre (6, 257.077) between (7.65, 257.077) and (4.35, 257.077); A9 r 1.65 centre (6, 280.022) between (7.65, 280.022) and (4.35, 280.022); A10 r 1.65 centre (6, 275.022) between (4.35, 275.022) and (7.65, 275.022); A11 r 1.65 centre (28.945, 257.077) between (30.595, 257.077) and (27.295, 257.077); A12 r 1.65 centre (28.945, 252.077) between (27.295, 252.077) and (30.595, 252.077); A13 r 3 centre (20.042, 267.849) between (23.042, 267.876) and (17.042, 267.821); A14 r 3 centre (20.079, 263.849) between (17.079, 263.821) and (23.078, 263.876); A15 r 3 centre (31.94, 275.728) between (28.94, 275.728) and (34.94, 275.728); A16 r 3 centre (31.94, 279.728) between (34.94, 279.728) and (28.94, 279.728); A17 r 3.5 centre (26, 274.288) between (29.5, 274.288) and (22.5, 274.288); A18 r 3.5 centre (26, 269.288) between (22.5, 269.288) and (29.5, 269.288); 5 further points
  constraints: 48 end point, 26 tangent, 24 point on circle, 13 centre point, 7 parallel, 6 midpoint, 3 equal length, 3 equal radius, 3 vertical, 1 coincident, 1 perpendicular, 1 point on line
  dimensions: "d962" = 1.65 radius of A8; "d963" = 5 distance of L8.start L8.end; "d965" = 6 diameter of C4; "d966" = 2 distance of C4.centre L14.end; "d967" = 2.5 distance of C6.centre L21.end
extrude "Выдавливание117" cut sketch "Эскиз146" distance "d968" = 4; taper "d969" = 0 deg; dims "d103" = 44
fillet "Сопряжение50" dims "d970" = 2
sketch "Эскиз147"
  geometry: L1 (10.45, 9.238)-(41.55, 9.238); L2 (41.55, 9.238)-(41.55, 40.338); L3 (41.55, 40.338)-(10.45, 40.338); L4 (10.45, 40.338)-(10.45, 9.238); L5 (10.45, 7.238)-(10.45, 11.238); L6 (11.95, 7.238)-(11.95, 11.238); L7 (8.95, 11.238)-(8.95, 7.238); L8 (10.45, 38.338)-(10.45, 42.338); L9 (11.95, 38.338)-(11.95, 42.338); L10 (8.95, 42.338)-(8.95, 38.338); L11 (41.55, 7.238)-(41.55, 11.238); L12 (43.05, 7.238)-(43.05, 11.238); L13 (40.05, 11.238)-(40.05, 7.238); L14 (41.55, 38.338)-(41.55, 42.338); L15 (43.05, 38.338)-(43.05, 42.338); L16 (40.05, 42.338)-(40.05, 38.338); L17 (26, 22.788)-(26, 26.788); L18 (30, 22.788)-(30, 26.788); L19 (22, 26.788)-(22, 22.788); C1 r 1.5 at (10.45, 9.238) reference; C2 r 1.5 at (10.45, 40.338) reference; C3 r 4 at (26, 24.788) reference; C4 r 1.5 at (41.55, 9.238) reference; C5 r 1.5 at (41.55, 40.338) reference; A1 r 1.5 centre (10.45, 7.238) between (8.95, 7.238) and (11.95, 7.238); A2 r 1.5 centre (10.45, 11.238) between (11.95, 11.238) and (8.95, 11.238); A3 r 1.5 centre (10.45, 38.338) between (8.95, 38.338) and (11.95, 38.338); A4 r 1.5 centre (10.45, 42.338) between (11.95, 42.338) and (8.95, 42.338); A5 r 1.5 centre (41.55, 7.238) between (40.05, 7.238) and (43.05, 7.238); A6 r 1.5 centre (41.55, 11.238) between (43.05, 11.238) and (40.05, 11.238); A7 r 1.5 centre (41.55, 38.338) between (40.05, 38.338) and (43.05, 38.338); A8 r 1.5 centre (41.55, 42.338) between (43.05, 42.338) and (40.05, 42.338); A9 r 4 centre (26, 22.788) between (22, 22.788) and (30, 22.788); A10 r 4 centre (26, 26.788) between (30, 26.788) and (22, 26.788); 1 further point
  constraints: 48 end point, 20 point on circle, 10 centre point, 10 tangent, 4 parallel, 2 horizontal, 2 midpoint, 2 vertical, 1 perpendicular, 1 point on line, 33 other
  dimensions: "d971" = 2 distance of L1.start L5.end; "d972" = 31.1 distance of L3.end L1.start (derived); "d975" = 31.1 distance of L6.start L9.start (derived); "d978" = 31.1 distance of L6.start L12.start (derived); "d981" = 2 distance of C3.centre L17.end
extrude "Выдавливание118" cut sketch "Эскиз147" distance "d982" = 4; taper "d983" = 0 deg
sketch "Эскиз148"
  geometry: L1 (5.657, 3.657)-(5.657, 7.657); L2 (4.157, 3.657)-(4.157, 7.657); L3 (7.157, 7.657)-(7.157, 3.657); L4 (-12.99, 5.5)-(-12.99, 9.5); L5 (-14.49, 5.5)-(-14.49, 9.5); L6 (-11.49, 9.5)-(-11.49, 5.5); L7 (0, -13)-(0, -17); L8 (-1.5, -13)-(-1.5, -17); L9 (1.5, -17)-(1.5, -13); C1 r 1.5 at (5.657, 5.657) reference; C2 r 1.5 at (0, -15) reference; C3 r 1.5 at (-12.99, 7.5) reference; A1 r 1.5 centre (5.657, 3.657) between (4.157, 3.657) and (7.157, 3.657); A2 r 1.5 centre (5.657, 7.657) between (7.157, 7.657) and (4.157, 7.657); A3 r 1.5 centre (-12.99, 5.5) between (-14.49, 5.5) and (-11.49, 5.5); A4 r 1.5 centre (-12.99, 9.5) between (-11.49, 9.5) and (-14.49, 9.5); A5 r 1.5 centre (0, -13) between (1.5, -13) and (-1.5, -13); A6 r 1.5 centre (0, -17) between (-1.5, -17) and (1.5, -17); 2 further points
  constraints: 24 end point, 13 tangent, 12 point on circle, 6 centre point, 6 parallel, 3 midpoint, 2 equal radius, 2 vertical, 1 coincident
  dimensions: "d984" = 2 distance of C1.centre L1.end
extrude "Выдавливание119" cut sketch "Эскиз148" distance "d985" = 4; taper "d986" = 0 deg
sketch "Эскиз149"
  geometry: L1 (-11.49, 9.5)-(-11.49, 5.5) reference; L2 (-14.49, 5.5)-(-14.49, 9.5) reference; L3 (-1.5, -17)-(-1.5, -13) reference; L4 (1.5, -13)-(1.5, -17) reference; L5 (7.157, 7.657)-(7.157, 3.657) reference; L6 (4.157, 3.657)-(4.157, 7.657) reference; L7 (-3.85, 15.824)-(-4.5, 15.824) reference; L8 (-5.5, 16.824)-(-5.5, 24.024) reference; L9 (-4.5, 25.024)-(4.5, 25.024) reference; L10 (5.5, 24.024)-(5.5, 16.824) reference; L11 (4.5, 15.824)-(3.85, 15.824) reference; L12 (2.85, 14.824)-(2.85, 9.748) reference; L13 (1.85, 8.748)-(-1.85, 8.748) reference; L14 (-2.85, 9.748)-(-2.85, 14.824) reference; L15 (4.05, 2.5)-(4.05, -2.5) reference; L16 (-4.05, -2.5)-(-4.05, 2.5) reference; L17 (-2.85, 212.872)-(-2.85, 217.948) reference; L18 (-1.85, 218.948)-(1.85, 218.948) reference; L19 (2.85, 217.948)-(2.85, 212.872) reference; L20 (3.85, 211.872)-(4.5, 211.872) reference; L21 (5.5, 210.872)-(5.5, 203.672) reference; L22 (4.5, 202.672)-(-4.5, 202.672) reference; L23 (-5.5, 203.672)-(-5.5, 210.872) reference; L24 (-4.5, 211.872)-(-3.85, 211.872) reference; L25 (6.35, 242.136)-(6.35, 234.136) reference; L26 (14.45, 234.136)-(14.45, 242.136) reference; L27 (16.9, 230.736)-(21, 230.736) reference; L28 (21, 230.736)-(21, 255.636) reference; L29 (14.592, 261.623)-(-117.526, 252.613) reference; L30 (-117.526, 252.613)-(-124, 246.139) reference; L31 (-124, 246.139)-(-124, -18.443) reference; L32 (-124, -18.443)-(-117.526, -24.917) reference; L33 (-117.526, -24.917)-(14.592, -33.927) reference; L34 (21, -27.94)-(21, -3.04) reference; L35 (21, -3.04)-(16.9, -3.04) reference; L36 (16.9, -3.04)-(16.9, 27.16) reference; L37 (16.9, 27.16)-(21, 27.16) reference; L38 (21, 27.16)-(21, 64.819) reference; L39 (21, 64.819)-(16.9, 64.819) reference; L40 (16.9, 64.819)-(16.9, 95.019) reference; L41 (16.9, 95.019)-(21, 95.019) reference; L42 (21, 95.019)-(21, 132.677) reference; L43 (21, 132.677)-(16.9, 132.677) reference; L44 (16.9, 132.677)-(16.9, 162.877) reference; L45 (16.9, 162.877)-(21, 162.877) reference; L46 (21, 162.877)-(21, 200.536) reference; L47 (21, 200.536)-(16.9, 200.536) reference; L48 (16.9, 200.536)-(16.9, 230.736) reference; L49 (-103.85, 213.848)-(-96.15, 213.848) reference; L50 (-103.85, 216.33)-(-103.85, 213.848) reference; L51 (-96.15, 213.848)-(-96.15, 216.33) reference; L52 (-96.15, 13.848)-(-103.85, 13.848) reference; L53 (-96.15, 11.366)-(-96.15, 13.848) reference; L54 (-103.85, 13.848)-(-103.85, 11.366) reference; L55 (-92.5, 204.772)-(-92.5, 209.772) reference; L56 (-107.5, 204.772)-(-92.5, 204.772) reference; L57 (-107.5, 209.772)-(-107.5, 204.772) reference; L58 (-92.5, 209.772)-(-107.5, 209.772) reference; L59 (-92.5, 17.924)-(-92.5, 22.924) reference; L60 (-107.5, 17.924)-(-92.5, 17.924) reference; L61 (-107.5, 22.924)-(-107.5, 17.924) reference; L62 (-92.5, 22.924)-(-107.5, 22.924) reference; L63 (1.65, 245.196)-(1.65, 240.196) reference; L64 (-1.65, 240.196)-(-1.65, 245.196) reference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; C1 r 2.4 at (-115.55, 15.55) reference; C2 r 2.4 at (-84.45, -15.55) reference; C3 r 2.4 at (-115.55, 243.246) reference; C4 r 2.4 at (-84.45, 212.146) reference; C5 r 2.4 at (-84.45, 243.246) reference; C6 r 2.4 at (-115.55, 212.146) reference; C7 r 2.4 at (-84.45, 15.55) reference; C8 r 2.4 at (-115.55, -15.55) reference; A1 r 1.5 centre (-12.99, 5.5) between (-14.49, 5.5) and (-11.49, 5.5) reference; A2 r 1.5 centre (-12.99, 9.5) between (-11.49, 9.5) and (-14.49, 9.5) reference; A3 r 1.5 centre (0, -13) between (1.5, -13) and (-1.5, -13) reference; A4 r 1.5 centre (0, -17) between (-1.5, -17) and (1.5, -17) reference; A5 r 1.5 centre (5.657, 3.657) between (4.157, 3.657) and (7.157, 3.657) reference; A6 r 1.5 centre (5.657, 7.657) between (7.157, 7.657) and (4.157, 7.657) reference; A7 r 1 centre (-3.85, 14.824) between (-2.85, 14.824) and (-3.85, 15.824) reference; A8 r 1 centre (-4.5, 16.824) between (-5.5, 16.824) and (-4.5, 15.824) reference; A9 r 1 centre (-4.5, 24.024) between (-4.5, 25.024) and (-5.5, 24.024) reference; A10 r 1 centre (4.5, 24.024) between (5.5, 24.024) and (4.5, 25.024) reference; A11 r 1 centre (4.5, 16.824) between (4.5, 15.824) and (5.5, 16.824) reference; A12 r 1 centre (3.85, 14.824) between (3.85, 15.824) and (2.85, 14.824) reference; A13 r 1 centre (1.85, 9.748) between (1.85, 8.748) and (2.85, 9.748) reference; A14 r 1 centre (-1.85, 9.748) between (-2.85, 9.748) and (-1.85, 8.748) reference; A15 r 4.05 centre (0, -2.5) between (-4.05, -2.5) and (4.05, -2.5) reference; A16 r 4.05 centre (0, 2.5) between (4.05, 2.5) and (-4.05, 2.5) reference; A17 r 1 centre (-3.85, 212.872) between (-3.85, 211.872) and (-2.85, 212.872) reference; A18 r 1 centre (-1.85, 217.948) between (-1.85, 218.948) and (-2.85, 217.948) reference; A19 r 1 centre (1.85, 217.948) between (2.85, 217.948) and (1.85, 218.948) reference; A20 r 1 centre (3.85, 212.872) between (2.85, 212.872) and (3.85, 211.872) reference; A21 r 1 centre (4.5, 210.872) between (5.5, 210.872) and (4.5, 211.872) reference; A22 r 1 centre (4.5, 203.672) between (4.5, 202.672) and (5.5, 203.672) reference; A23 r 1 centre (-4.5, 203.672) between (-5.5, 203.672) and (-4.5, 202.672) reference; A24 r 1 centre (-4.5, 210.872) between (-4.5, 211.872) and (-5.5, 210.872) reference; A25 r 4.05 centre (10.4, 242.136) between (14.45, 242.136) and (6.35, 242.136) reference; A26 r 4.05 centre (10.4, 234.136) between (6.35, 234.136) and (14.45, 234.136) reference; A27 r 6 centre (15, 255.636) between (21, 255.636) and (14.592, 261.623) reference; A28 r 6 centre (15, -27.94) between (14.592, -33.927) and (21, -27.94) reference; A29 r 12 centre (-100, 227.696) between (-96.15, 216.33) and (-103.85, 216.33) reference; A30 r 12 centre (-100, 0) between (-103.85, 11.366) and (-96.15, 11.366) reference; A31 r 1.65 centre (0, 245.196) between (1.65, 245.196) and (-1.65, 245.196) reference; A32 r 1.65 centre (0, 240.196) between (-1.65, 240.196) and (1.65, 240.196) reference; A33 r 1.65 centre (12.99, 217.696) between (11.34, 217.696) and (14.64, 217.696) reference; A34 r 1.65 centre (12.99, 222.696) between (14.64, 222.696) and (11.34, 222.696) reference; A35 r 1.65 centre (-12.99, 222.696) between (-11.34, 222.696) and (-14.64, 222.696) reference; A36 r 1.65 centre (-12.99, 217.696) between (-14.64, 217.696) and (-11.34, 217.696) reference; A37 r 4.05 centre (0, 225.196) between (-4.05, 225.196) and (4.05, 225.196) reference; A38 r 4.05 centre (0, 230.196) between (4.05, 230.196) and (-4.05, 230.196) reference; 1 further point
extrude "Выдавливание120" join sketch "Эскиз149" distance "d987" = 4; taper "d988" = 0 deg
